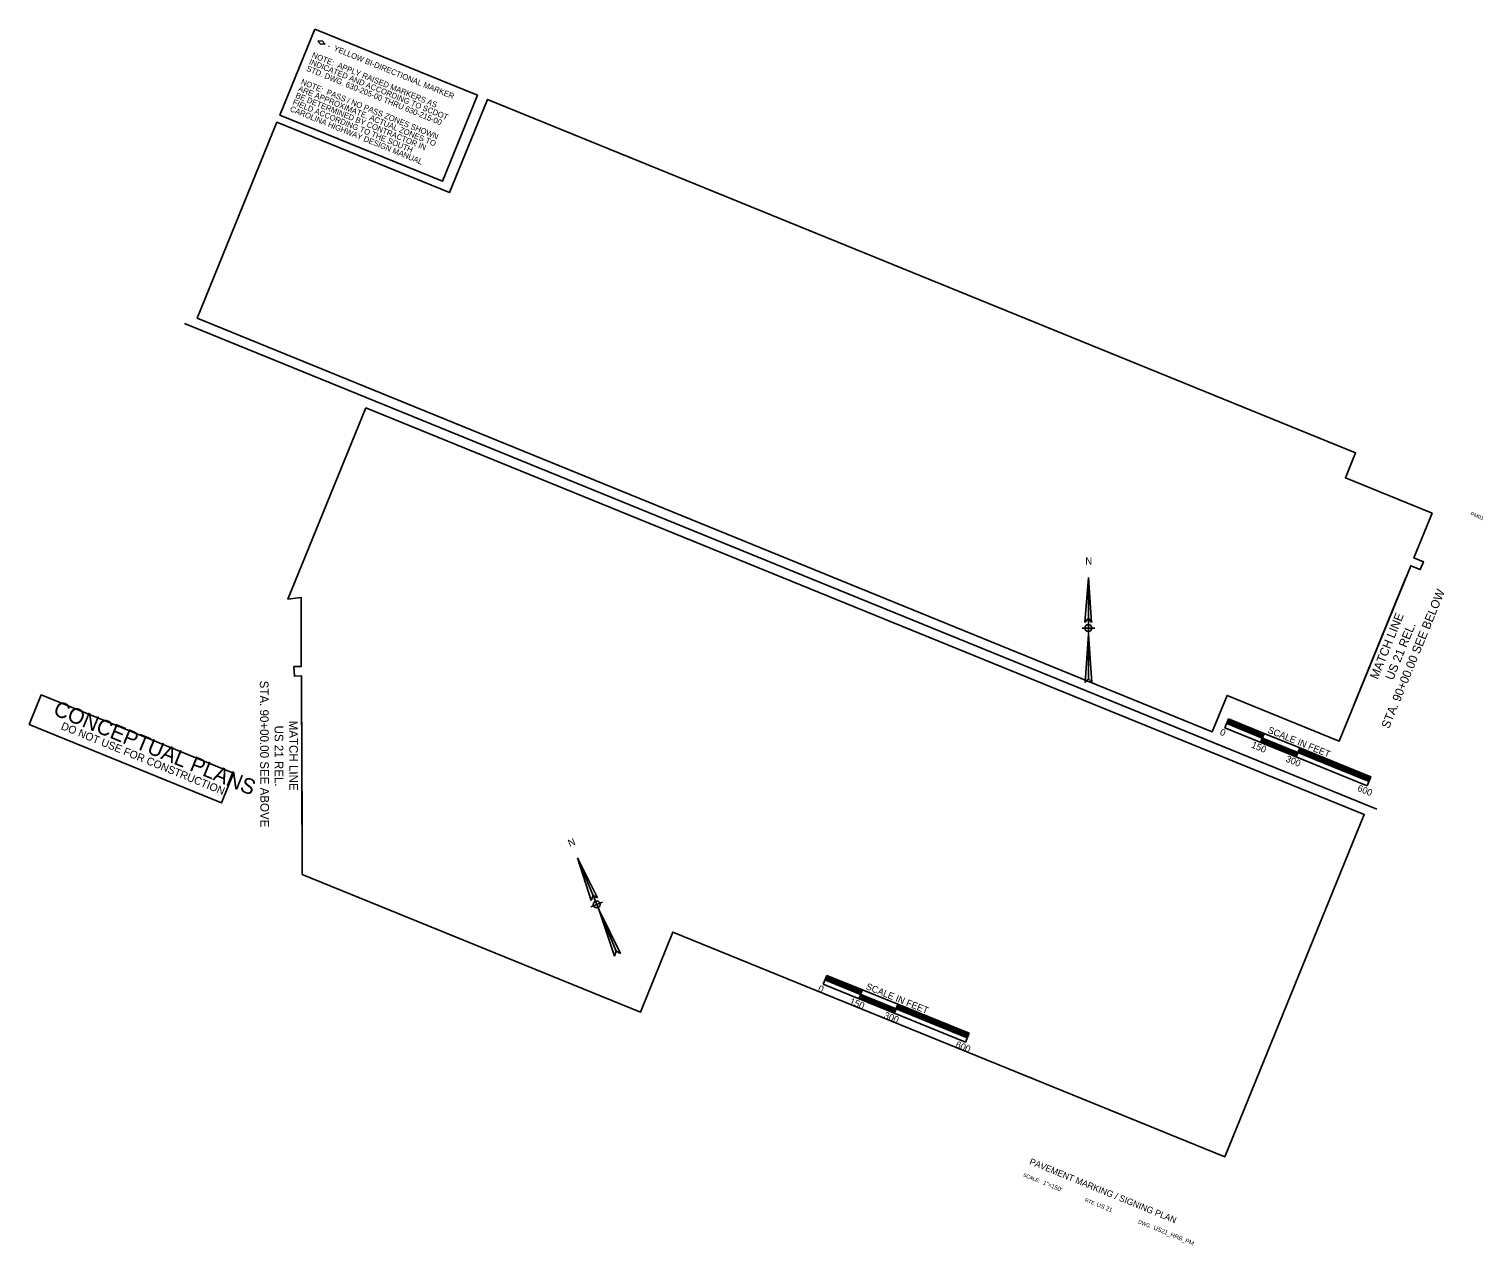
# Model space of a CAD drawing. Extents: x 2163365 to 2169041, y 204877 to 209623.
import ezdxf

# ---------------------------------------------------------------- set-up
doc = ezdxf.new("R2010")
doc.units = 0
for name, color, linetype in [('North Arrow', 7, 'Continuous'), ('RD_SHT_Bndy', 7, 'Continuous'), ('RD_SHT_MatchLine', 7, 'Continuous'), ('RD_SHT_ShtClip', 7, 'Continuous'), ('RD_SHT_TX', 7, 'Continuous'), ('RD_SHT_Typical', 7, 'Continuous'), ('TR PM PAVEMENT MARKING GENERAL', 7, 'Continuous'), ('TR PM PAVEMENT MARKING NOTES', 7, 'Continuous'), ('TR PM PERMANENT YELLOW PAVEMENT MARKERS BI-DIR - 4 IN X 4 IN', 7, 'Continuous')]:
    doc.layers.add(name, color=color, linetype=linetype)

msp = doc.modelspace()

# ---------------------------------------------------------------- linework, layer by layer
at = {"layer": 'North Arrow'}
for p, q in [((2167500.4, 207482.5), (2167486.6, 207307.6)), ((2167500.4, 207482.5), (2167513.2, 207307.5)), ((2167500.4, 207482.5), (2167500.4, 207087.7)), ((2167475.6, 207285.4), (2167525.1, 207285.4)), ((2167500.4, 207323.6), (2167486.6, 207307.6)), ((2167500.4, 207323.6), (2167513.2, 207307.5)), ((2167500.4, 207261.7), (2167487.4, 207072.6)), ((2167487.4, 207072.6), (2167500.4, 207261.7)), ((2167500.4, 207261.7), (2167513.6, 207072.7)), ((2167487.4, 207072.6), (2167500.4, 207087.7)), ((2167513.6, 207072.7), (2167500.4, 207087.7)), ((2165506, 206388.6), (2165560, 206221.7)), ((2165506, 206388.6), (2165584.6, 206231.7)), ((2165506, 206388.6), (2165656.5, 206023.6)), ((2165558.2, 206197), (2165604, 206215.8)), ((2165566.6, 206241.7), (2165560, 206221.7)), ((2165566.6, 206241.7), (2165584.6, 206231.7)), ((2165590.2, 206184.5), (2165650.2, 206004.7)), ((2165650.2, 206004.7), (2165590.2, 206184.5)), ((2165590.2, 206184.5), (2165674.5, 206014.8)), ((2165650.2, 206004.7), (2165656.5, 206023.6)), ((2165674.5, 206014.8), (2165656.5, 206023.6))]:
    msp.add_line(p, q, dxfattribs=at)
for centre in [(2167500.4, 207285.4), (2165581.1, 206206.4)]:
    msp.add_circle(centre, 13.3, dxfattribs=at)
at = {"layer": 'RD_SHT_Bndy'}
msp.add_line((2168626.1, 206578.6), (2163972.3, 208474), dxfattribs=at)
at = {"layer": 'RD_SHT_MatchLine'}
for p, q in [((2168536.1, 206982), (2168740, 207482.6)), ((2164430.6, 206512.8), (2164428.2, 207053.3))]:
    msp.add_line(p, q, dxfattribs=at)
at = {"layer": 'RD_SHT_ShtClip'}
for points in [[(2164021.2, 208494.6), (2167984, 206880.6), (2168041.7, 207022.2), (2168479.8, 206843.8), (2168758.7, 207528.5), (2168796.1, 207513.3), (2168808.6, 207544.1), (2168771.2, 207559.4), (2168842.3, 207733.7), (2168503.8, 207871.6), (2168543.4, 207968.8), (2165154.9, 209349), (2165006.7, 208985.1), (2164332.7, 209259.6)], [(2164680, 208145.3), (2164375.7, 207398.2), (2164426.7, 207404.7), (2164427.9, 207135.4), (2164398.9, 207134.8), (2164400.7, 207097.5), (2164428, 207098.9), (2164431.5, 206323.4), (2165751.5, 205785.7), (2165878.8, 206098.3), (2168032.6, 205221), (2168577.2, 206558)]]:
    msp.add_lwpolyline(points, close=True, dxfattribs=at)
at = {"layer": 'RD_SHT_TX'}
for p, q in [((2168047.9, 206930.5), (2168033.8, 206895.7)), ((2168033.8, 206895.7), (2168589.4, 206669.4)), ((2168040.6, 206912.4), (2168129.5, 206876.2)), ((2168040.6, 206912.4), (2168179.5, 206855.8)), ((2168040.6, 206912.4), (2168179.5, 206855.8)), ((2168041.1, 206913.8), (2168180, 206857.2)), ((2168041.1, 206913.8), (2168180, 206857.2)), ((2168041.7, 206915.2), (2168180.6, 206858.6)), ((2168041.7, 206915.2), (2168180.6, 206858.6)), ((2168042.3, 206916.6), (2168181.2, 206860)), ((2168042.3, 206916.6), (2168181.2, 206860)), ((2168042.8, 206918), (2168181.7, 206861.4)), ((2168042.8, 206918), (2168181.7, 206861.4)), ((2168043.4, 206919.3), (2168182.3, 206862.8)), ((2168043.4, 206919.3), (2168182.3, 206862.8)), ((2168044, 206920.7), (2168182.9, 206864.2)), ((2168044, 206920.7), (2168182.9, 206864.2)), ((2168044.5, 206922.1), (2168183.4, 206865.5)), ((2168044.5, 206922.1), (2168183.4, 206865.5)), ((2168045.1, 206923.5), (2168184, 206866.9)), ((2168045.1, 206923.5), (2168184, 206866.9)), ((2168045.7, 206924.9), (2168184.6, 206868.3)), ((2168045.7, 206924.9), (2168184.6, 206868.3)), ((2168046.2, 206926.3), (2168185.1, 206869.7)), ((2168046.2, 206926.3), (2168185.1, 206869.7)), ((2168046.8, 206927.7), (2168185.7, 206871.1)), ((2168046.8, 206927.7), (2168185.7, 206871.1)), ((2168047.4, 206929.1), (2168186.3, 206872.5)), ((2168047.4, 206929.1), (2168186.3, 206872.5)), ((2168047.9, 206930.5), (2168186.8, 206873.9)), ((2168129.5, 206876.2), (2168487.9, 206730.2)), ((2168186.8, 206873.9), (2168172.7, 206839.1)), ((2168173.3, 206840.5), (2168312.2, 206784)), ((2168173.3, 206840.5), (2168312.2, 206784)), ((2168173.8, 206841.9), (2168312.7, 206785.3)), ((2168173.8, 206841.9), (2168312.7, 206785.3)), ((2168174.4, 206843.3), (2168313.3, 206786.7)), ((2168174.4, 206843.3), (2168313.3, 206786.7)), ((2168175, 206844.7), (2168313.9, 206788.1)), ((2168175, 206844.7), (2168313.9, 206788.1)), ((2168175.5, 206846.1), (2168314.4, 206789.5)), ((2168175.5, 206846.1), (2168314.4, 206789.5)), ((2168176.1, 206847.5), (2168315, 206790.9)), ((2168176.1, 206847.5), (2168315, 206790.9)), ((2168176.7, 206848.9), (2168315.6, 206792.3)), ((2168176.7, 206848.9), (2168315.6, 206792.3)), ((2168177.2, 206850.3), (2168316.1, 206793.7)), ((2168177.2, 206850.3), (2168316.1, 206793.7)), ((2168177.8, 206851.7), (2168316.7, 206795.1)), ((2168177.8, 206851.7), (2168316.7, 206795.1)), ((2168178.3, 206853), (2168317.3, 206796.5)), ((2168178.3, 206853), (2168317.3, 206796.5)), ((2168178.9, 206854.4), (2168317.8, 206797.8)), ((2168178.9, 206854.4), (2168317.8, 206797.8)), ((2168179.5, 206855.8), (2168318.4, 206799.2)), ((2168186.8, 206873.9), (2168186.8, 206873.9)), ((2168186.8, 206873.9), (2168325.8, 206817.3)), ((2168325.8, 206817.3), (2168311.6, 206782.6)), ((2168318.4, 206799.2), (2168596.2, 206686.1)), ((2168319, 206800.6), (2168596.8, 206687.5)), ((2168319, 206800.6), (2168596.8, 206687.5)), ((2168319.5, 206802), (2168597.4, 206688.9)), ((2168319.5, 206802), (2168597.4, 206688.9)), ((2168320.1, 206803.4), (2168597.9, 206690.2)), ((2168320.1, 206803.4), (2168597.9, 206690.2)), ((2168320.7, 206804.8), (2168598.5, 206691.6)), ((2168320.7, 206804.8), (2168598.5, 206691.6)), ((2168321.2, 206806.2), (2168599.1, 206693)), ((2168321.2, 206806.2), (2168599.1, 206693)), ((2168321.8, 206807.6), (2168599.6, 206694.4)), ((2168321.8, 206807.6), (2168599.6, 206694.4)), ((2168322.4, 206809), (2168600.2, 206695.8)), ((2168322.4, 206809), (2168600.2, 206695.8)), ((2168322.9, 206810.4), (2168600.8, 206697.2)), ((2168322.9, 206810.4), (2168600.8, 206697.2)), ((2168323.5, 206811.7), (2168601.3, 206698.6)), ((2168323.5, 206811.7), (2168601.3, 206698.6)), ((2168324.1, 206813.1), (2168601.9, 206700)), ((2168324.1, 206813.1), (2168601.9, 206700)), ((2168324.6, 206814.5), (2168602.5, 206701.4)), ((2168324.6, 206814.5), (2168602.5, 206701.4)), ((2168325.2, 206815.9), (2168603, 206702.7)), ((2168325.2, 206815.9), (2168603, 206702.7)), ((2168325.8, 206817.3), (2168603.6, 206704.1)), ((2168596.2, 206686.1), (2168487.9, 206730.2)), ((2168603.6, 206704.1), (2168589.4, 206669.4)), ((2168589.4, 206669.4), (2168589.4, 206669.4)), ((2166479.3, 205929.6), (2166465.1, 205894.9)), ((2166471.9, 205911.6), (2166560.8, 205875.4)), ((2166471.9, 205911.6), (2166610.8, 205855)), ((2166471.9, 205911.6), (2166610.8, 205855)), ((2166472.5, 205913), (2166611.4, 205856.4)), ((2166472.5, 205913), (2166611.4, 205856.4)), ((2166473, 205914.4), (2166612, 205857.8)), ((2166473, 205914.4), (2166612, 205857.8)), ((2166473.6, 205915.7), (2166612.5, 205859.2)), ((2166473.6, 205915.7), (2166612.5, 205859.2)), ((2166474.2, 205917.1), (2166613.1, 205860.6)), ((2166474.2, 205917.1), (2166613.1, 205860.6)), ((2166474.7, 205918.5), (2166613.7, 205861.9)), ((2166474.7, 205918.5), (2166613.7, 205861.9)), ((2166475.3, 205919.9), (2166614.2, 205863.3)), ((2166475.3, 205919.9), (2166614.2, 205863.3)), ((2166475.9, 205921.3), (2166614.8, 205864.7)), ((2166475.9, 205921.3), (2166614.8, 205864.7)), ((2166476.4, 205922.7), (2166615.3, 205866.1)), ((2166476.4, 205922.7), (2166615.3, 205866.1)), ((2166477, 205924.1), (2166615.9, 205867.5)), ((2166477, 205924.1), (2166615.9, 205867.5)), ((2166477.6, 205925.5), (2166616.5, 205868.9)), ((2166477.6, 205925.5), (2166616.5, 205868.9)), ((2166478.1, 205926.9), (2166617, 205870.3)), ((2166478.1, 205926.9), (2166617, 205870.3)), ((2166478.7, 205928.3), (2166617.6, 205871.7)), ((2166478.7, 205928.3), (2166617.6, 205871.7)), ((2166479.3, 205929.6), (2166618.2, 205873.1)), ((2166465.1, 205894.9), (2167020.8, 205668.6)), ((2166560.8, 205875.4), (2166919.2, 205729.4)), ((2166618.2, 205873.1), (2166604, 205838.3)), ((2166610.8, 205855), (2166749.7, 205798.4)), ((2166618.2, 205873.1), (2166618.2, 205873.1)), ((2166618.2, 205873.1), (2166757.1, 205816.5)), ((2166604.6, 205839.7), (2166743.5, 205783.1)), ((2166604.6, 205839.7), (2166743.5, 205783.1)), ((2166605.2, 205841.1), (2166744.1, 205784.5)), ((2166605.2, 205841.1), (2166744.1, 205784.5)), ((2166605.7, 205842.5), (2166744.6, 205785.9)), ((2166605.7, 205842.5), (2166744.6, 205785.9)), ((2166606.3, 205843.9), (2166745.2, 205787.3)), ((2166606.3, 205843.9), (2166745.2, 205787.3)), ((2166606.9, 205845.3), (2166745.8, 205788.7)), ((2166606.9, 205845.3), (2166745.8, 205788.7)), ((2166607.4, 205846.7), (2166746.3, 205790.1)), ((2166607.4, 205846.7), (2166746.3, 205790.1)), ((2166608, 205848.1), (2166746.9, 205791.5)), ((2166608, 205848.1), (2166746.9, 205791.5)), ((2166608.6, 205849.4), (2166747.5, 205792.9)), ((2166608.6, 205849.4), (2166747.5, 205792.9)), ((2166609.1, 205850.8), (2166748, 205794.2)), ((2166609.1, 205850.8), (2166748, 205794.2)), ((2166609.7, 205852.2), (2166748.6, 205795.6)), ((2166609.7, 205852.2), (2166748.6, 205795.6)), ((2166610.3, 205853.6), (2166749.2, 205797)), ((2166610.3, 205853.6), (2166749.2, 205797)), ((2166757.1, 205816.5), (2166743, 205781.7)), ((2166749.7, 205798.4), (2167027.6, 205685.3)), ((2166750.3, 205799.8), (2167028.1, 205686.6)), ((2166750.3, 205799.8), (2167028.1, 205686.6)), ((2166750.9, 205801.2), (2167028.7, 205688)), ((2166750.9, 205801.2), (2167028.7, 205688)), ((2166751.4, 205802.6), (2167029.3, 205689.4)), ((2166751.4, 205802.6), (2167029.3, 205689.4)), ((2166752, 205804), (2167029.8, 205690.8)), ((2166752, 205804), (2167029.8, 205690.8)), ((2166752.6, 205805.4), (2167030.4, 205692.2)), ((2166752.6, 205805.4), (2167030.4, 205692.2)), ((2166753.1, 205806.8), (2167031, 205693.6)), ((2166753.1, 205806.8), (2167031, 205693.6)), ((2166753.7, 205808.1), (2167031.5, 205695)), ((2166753.7, 205808.1), (2167031.5, 205695)), ((2166754.3, 205809.5), (2167032.1, 205696.4)), ((2166754.3, 205809.5), (2167032.1, 205696.4)), ((2166754.8, 205810.9), (2167032.7, 205697.8)), ((2166754.8, 205810.9), (2167032.7, 205697.8)), ((2166755.4, 205812.3), (2167033.2, 205699.1)), ((2166755.4, 205812.3), (2167033.2, 205699.1)), ((2166756, 205813.7), (2167033.8, 205700.5)), ((2166756, 205813.7), (2167033.8, 205700.5)), ((2166756.5, 205815.1), (2167034.4, 205701.9)), ((2166756.5, 205815.1), (2167034.4, 205701.9)), ((2166757.1, 205816.5), (2167034.9, 205703.3)), ((2167027.6, 205685.3), (2166919.2, 205729.4)), ((2167034.9, 205703.3), (2167020.8, 205668.6)), ((2167020.8, 205668.6), (2167020.8, 205668.6))]:
    msp.add_line(p, q, dxfattribs=at)
at = {"layer": 'RD_SHT_Typical'}
msp.add_lwpolyline([(2163365.1, 206908.8), (2163412.2, 207024.3), (2164163.4, 206718.4), (2164116.3, 206602.8)], close=True, dxfattribs=at)
at = {"layer": 'TR PM PAVEMENT MARKING GENERAL'}
msp.add_lwpolyline([(2164480.9, 209623.5), (2165115.5, 209365), (2164978.8, 209029.5), (2164344.3, 209288)], close=True, dxfattribs=at)
at = {"layer": 'TR PM PERMANENT YELLOW PAVEMENT MARKERS BI-DIR - 4 IN X 4 IN'}
msp.add_lwpolyline([(2164492.4, 209576.4), (2164503.3, 209564), (2164519.8, 209565.3), (2164508.9, 209577.7)], close=True, dxfattribs=at)

# ---------------------------------------------------------------- texts
at = {"layer": 'North Arrow'}
for rotation, p in [(360, (2167488.5, 207532.8)), (22.4136, (2165475.8, 206430.6))]:
    msp.add_text('N', height=28.1, rotation=rotation, dxfattribs=at).set_placement(p)
at = {"layer": 'RD_SHT_MatchLine'}
for s, rotation, p in [('STA. 90+00.00 SEE BELOW', 67.8388, (2168674, 206890.4)), ('MATCH LINE', 67.8388, (2168629.6, 207082.9)), ('US 21 REL.', 67.8388, (2168689.5, 207079.2)), ('STA. 90+00.00 SEE ABOVE', 270.2524, (2164265.9, 207080.1)), ('US 21 REL.', 270.2524, (2164323.5, 206904.6)), ('MATCH LINE', 270.2524, (2164380.3, 206923.9))]:
    msp.add_text(s, height=33.75, rotation=rotation, dxfattribs=at).set_placement(p)
at = {"layer": 'RD_SHT_TX'}
for s, height, p in [('PM01', 14.99, (2168990.6, 207726)), ('0', 26.2, (2168011.5, 206869.5)), ('SCALE IN FEET', 26.25, (2168198.2, 206877.3)), ('150', 26.25, (2168134.3, 206819.3)), ('300', 26.25, (2168268.5, 206764.9)), ('600', 26.25, (2168548.2, 206650.7)), ('0', 26.2, (2166442.9, 205868.7)), ('SCALE IN FEET', 26.25, (2166629.5, 205876.5)), ('150', 26.25, (2166565.6, 205818.5)), ('300', 26.25, (2166699.8, 205764.1)), ('600', 26.25, (2166979.6, 205649.9)), ('PAVEMENT MARKING / SIGNING PLAN', 25.026, (2167268, 205193.1)), ('SCALE:', 14.25, (2167243.6, 205145.6)), ('1"=150\'', 16.87, (2167321.5, 205113.8)), ('RTE.', 14.25, (2167484.8, 205047.3)), ('US 21', 16.87, (2167530.4, 205028.7)), ('DWG.', 14.25, (2167693.1, 204962.5)), ('US21_HRB_PM', 16.875, (2167753, 204938.1))]:
    msp.add_text(s, height=height, rotation=337.8388, dxfattribs=at).set_placement(p)
at = {"layer": 'RD_SHT_Typical'}
for s, height, p in [('CONCEPTUAL PLANS', 60.48, (2163455.5, 206948)), ('DO NOT USE FOR CONSTRUCTION', 30.24, (2163487.1, 206891.5))]:
    msp.add_text(s, height=height, rotation=337.8388, dxfattribs=at).set_placement(p)
at = {"layer": 'TR PM PAVEMENT MARKING NOTES'}
for s, p in [('-  YELLOW BI-DIRECTIONAL MARKER', (2164527.6, 209549.9)), ('INDICATED AND ACCORDING TO SCDOT', (2164456.2, 209487.5)), ('NOTE:  APPLY RAISED MARKERS AS', (2164467, 209513.9)), ('STD. DWG. 630-205-00 THRU 630-215-00', (2164445.5, 209461.1)), ('BE DETERMINED BY CONTRACTOR IN ', (2164402.8, 209356.3)), ('ARE APPROXIMATE. ACTUAL ZONES TO ', (2164413.5, 209382.7)), ('NOTE:  PASS / NO PASS ZONES SHOWN', (2164424.3, 209409.1)), ('CAROLINA HIGHWAY DESIGN MANUAL', (2164381.3, 209303.6)), ('FIELD ACCORDING TO THE SOUTH ', (2164392, 209329.9))]:
    msp.add_text(s, height=22.2, rotation=337.8388, dxfattribs=at).set_placement(p)

doc.saveas('drawing.dxf')
